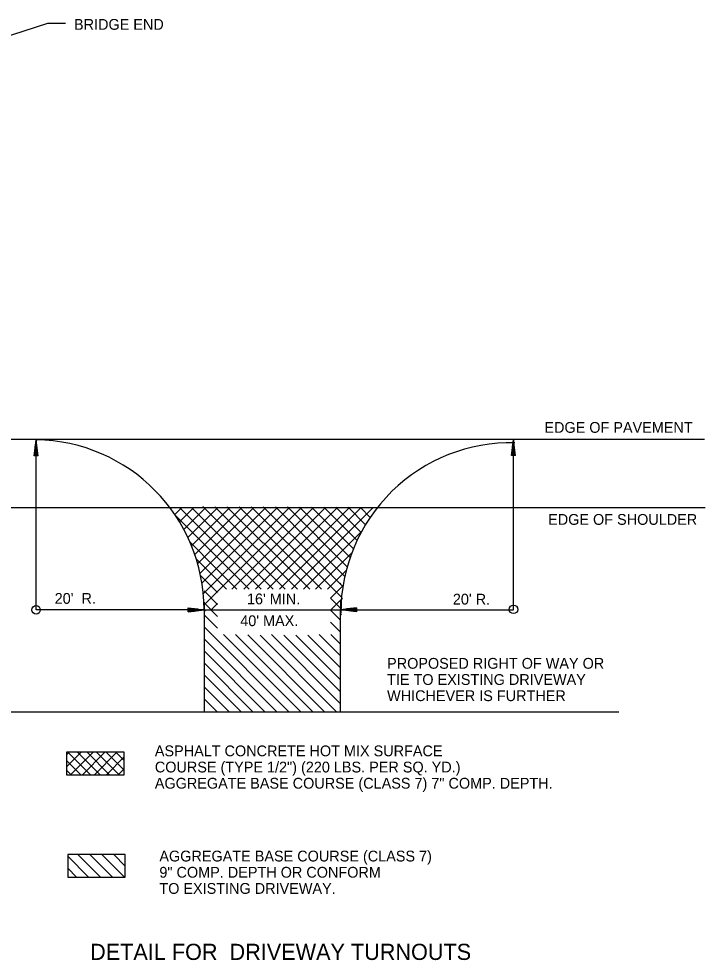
# Model space of a CAD drawing. Extents: x -2842 to 2681, y -2139 to 474.
# Drawn here: x -1653 to -1271, y -2139 to -1616 of the extents above; entities that cross this region are included whole.
import ezdxf

# ---------------------------------------------------------------- set-up
doc = ezdxf.new("R2010")
doc.units = 0
for name, color, linetype in [('B_County and Route', 7, 'Continuous'), ('B_Title Text', 7, 'Continuous'), ('R_Border', 7, 'Continuous'), ('R_Border Notes', 7, 'Continuous')]:
    doc.layers.add(name, color=color, linetype=linetype)

msp = doc.modelspace()

# ---------------------------------------------------------------- linework, layer by layer
at = {"layer": 'B_County and Route'}
for p, q in [((-1697.05, -1849.55), (-1271.3, -1849.55)), ((-1697.05, -1887.51), (-1270.98, -1887.51)), ((-1549.76, -1944.4), (-1549.76, -2001.23)), ((-1473.78, -2001.28), (-1473.78, -1944.17)), ((-1707.88, -2001.23), (-1318.99, -2001.23))]:
    msp.add_line(p, q, dxfattribs=at)
for points in [[(-1626.2, -2023.63), (-1626.2, -2036.17), (-1594.22, -2036.17), (-1594.22, -2023.63)], [(-1625.57, -2080.51), (-1625.57, -2093.05), (-1593.6, -2093.05), (-1593.6, -2080.51)]]:
    msp.add_lwpolyline(points, close=True, dxfattribs=at)
for centre, radius, start, end in [((-1644.4, -1944.55), 94.68, 0.0764, 89.2743), ((-1378.96, -1946.22), 94.72, 88.7538, 180)]:
    msp.add_arc(centre, radius, start, end, dxfattribs=at)
at = {"layer": 'B_Title Text'}
for p, q in [((-1516.65, -1907.12), (-1490.94, -1933)), ((-1503.31, -1907.18), (-1473.27, -1937.39)), ((-1554.04, -1916.3), (-1537.34, -1933)), ((-1543.32, -1921.14), (-1531.47, -1933)), ((-1484.84, -1919.09), (-1472.53, -1931.46)), ((-1551.64, -1925.36), (-1542.24, -1934.76)), ((-1549.76, -1933.91), (-1542.24, -1941.43)), ((-1549.76, -1940.24), (-1549.76, -1944.68)), ((-1549.76, -1940.58), (-1542.24, -1948.1)), ((-1479.42, -1937.9), (-1473.78, -1943.49)), ((-1473.78, -1938.93), (-1473.78, -1944.34)), ((-1549.76, -1947.25), (-1542.24, -1954.71)), ((-1479.42, -1944.57), (-1473.78, -1950.15)), ((-1479.42, -1951.24), (-1473.78, -1956.82)), ((-1549.76, -1953.92), (-1502.62, -2001.23)), ((-1549.76, -1960.59), (-1509.24, -2001.23)), ((-1538.88, -1958.13), (-1495.95, -2001.23)), ((-1532.21, -1958.13), (-1489.29, -2001.23)), ((-1525.42, -1958.36), (-1482.67, -2001.23)), ((-1518.53, -1958.59), (-1476, -2001.23)), ((-1512.31, -1958.13), (-1473.78, -1996.78)), ((-1505.36, -1958.48), (-1473.78, -1990.11)), ((-1498.69, -1958.48), (-1473.78, -1983.44)), ((-1492.02, -1958.53), (-1473.78, -1976.77)), ((-1485.75, -1958.13), (-1473.78, -1970.1)), ((-1479.14, -1958.13), (-1473.78, -1963.49)), ((-1549.76, -1967.2), (-1515.85, -2001.23)), ((-1549.76, -1973.87), (-1522.52, -2001.23)), ((-1549.76, -1980.54), (-1529.13, -2001.23)), ((-1549.76, -1987.2), (-1535.8, -2001.23)), ((-1549.76, -1993.87), (-1542.41, -2001.23))]:
    msp.add_line(p, q, dxfattribs=at)
for points in [[(-1566.01, -1891.44), (-1562.02, -1887.51)], [(-1563.44, -1887.51), (-1518.01, -1933)], [(-1563.39, -1895.49), (-1555.41, -1887.51)], [(-1560.99, -1899.77), (-1548.74, -1887.51)], [(-1558.71, -1904.16), (-1542.07, -1887.51)], [(-1556.77, -1887.51), (-1511.23, -1933)], [(-1556.72, -1908.77), (-1535.4, -1887.51)], [(-1554.89, -1913.62), (-1528.79, -1887.51)], [(-1553.3, -1918.63), (-1522.12, -1887.51)], [(-1551.99, -1923.99), (-1515.45, -1887.51)], [(-1550.9, -1929.58), (-1508.84, -1887.51)], [(-1550.5, -1887.06), (-1504.56, -1933)], [(-1550.16, -1935.45), (-1502.17, -1887.51)], [(-1543.78, -1887.11), (-1497.84, -1933)], [(-1541.04, -1933), (-1495.5, -1887.51)], [(-1537.05, -1887.11), (-1516.87, -1907.35)], [(-1534.37, -1933), (-1488.83, -1887.51)], [(-1530.27, -1887.17), (-1484.38, -1933)], [(-1527.7, -1933), (-1482.16, -1887.51)], [(-1523.54, -1887.17), (-1503.42, -1907.35)], [(-1521.09, -1933), (-1475.55, -1887.51)], [(-1516.82, -1887.17), (-1484.84, -1919.09)], [(-1514.42, -1933), (-1468.88, -1887.51)], [(-1510.09, -1887.23), (-1489.97, -1907.35)], [(-1507.75, -1933), (-1462.27, -1887.51)], [(-1503.36, -1887.23), (-1470.08, -1920.46)], [(-1501.08, -1933), (-1455.6, -1887.51)], [(-1496.58, -1887.28), (-1468.48, -1915.38)], [(-1489.91, -1887.28), (-1466.66, -1910.48)], [(-1483.19, -1887.28), (-1464.6, -1905.81)], [(-1476.4, -1887.28), (-1462.32, -1901.36)], [(-1469.62, -1887.34), (-1459.93, -1897.09)], [(-1462.78, -1887.51), (-1457.31, -1893.04)], [(-1565.49, -1892.24), (-1524.74, -1933)], [(-1494.47, -1933), (-1461.87, -1900.45)], [(-1557.51, -1906.89), (-1543.32, -1921.14)], [(-1489.97, -1907.35), (-1471.44, -1925.87)], [(-1487.8, -1933), (-1467.57, -1912.76)], [(-1481.13, -1933), (-1470.65, -1922.51)], [(-1549.76, -1928.1), (-1549.53, -1928.27)], [(-1479.42, -1937.9), (-1472.41, -1930.95)], [(-1474.29, -1929.63), (-1473.78, -1930.2)], [(-1549.76, -1941.66), (-1541.04, -1933)], [(-1549.76, -1934.76), (-1549.59, -1934.99)], [(-1474.29, -1936.47), (-1473.55, -1937.22)], [(-1549.76, -1941.49), (-1549.65, -1941.66)], [(-1545.77, -1944.4), (-1542.24, -1940.92)], [(-1479.25, -1944.4), (-1472.76, -1937.9)], [(-1549.65, -1944.74), (-1549.14, -1945.2)], [(-1474.29, -1943.2), (-1473.78, -1943.66)], [(-1474.01, -1946.56), (-1473.38, -1947.08)], [(-1626.2, -2025.05), (-1624.77, -2023.63)], [(-1626.2, -2031.66), (-1618.16, -2023.63)], [(-1625.52, -2023.63), (-1612.92, -2036.17)], [(-1624.03, -2036.17), (-1611.49, -2023.63)], [(-1620.16, -2023.63), (-1607.62, -2036.17)], [(-1617.42, -2036.17), (-1604.88, -2023.63)], [(-1614.86, -2023.63), (-1602.32, -2036.17)], [(-1610.75, -2036.17), (-1598.21, -2023.63)], [(-1609.5, -2023.63), (-1596.96, -2036.17)], [(-1604.2, -2023.63), (-1594.22, -2033.6)], [(-1598.9, -2023.63), (-1594.22, -2028.3)], [(-1626.2, -2028.24), (-1618.28, -2036.17)], [(-1604.08, -2036.17), (-1594.22, -2026.25)], [(-1626.2, -2033.54), (-1623.58, -2036.17)], [(-1597.47, -2036.17), (-1594.22, -2032.92)], [(-1625.57, -2081.48), (-1614, -2093.05)], [(-1619.93, -2080.51), (-1607.39, -2093.05)], [(-1613.26, -2080.51), (-1600.72, -2093.05)], [(-1606.59, -2080.51), (-1594.05, -2093.05)], [(-1599.98, -2080.51), (-1593.6, -2086.9)], [(-1625.57, -2088.15), (-1620.67, -2093.05)]]:
    msp.add_lwpolyline(points, dxfattribs=at)
at = {"layer": 'R_Border Notes'}
for p, q in [((-1644.33, -1858.72), (-1643.19, -1849.89)), ((-1643.41, -1858.72), (-1643.41, -1851.68)), ((-1643.19, -1944.4), (-1643.19, -1849.89)), ((-1643.19, -1849.89), (-1643.19, -1858.71)), ((-1642.04, -1858.71), (-1643.19, -1849.89)), ((-1642.96, -1858.71), (-1642.96, -1851.68)), ((-1378.76, -1858.6), (-1377.62, -1849.78)), ((-1377.84, -1858.6), (-1377.85, -1851.57)), ((-1377.62, -1944.4), (-1377.62, -1849.78)), ((-1377.62, -1849.78), (-1377.62, -1858.6)), ((-1376.47, -1858.6), (-1377.62, -1849.78)), ((-1377.39, -1858.6), (-1377.39, -1851.57)), ((-1644.1, -1858.72), (-1644.1, -1856.99)), ((-1643.87, -1858.72), (-1643.87, -1855.2)), ((-1643.64, -1858.72), (-1643.64, -1853.41)), ((-1642.73, -1858.72), (-1642.73, -1853.41)), ((-1642.49, -1858.71), (-1642.5, -1855.19)), ((-1642.26, -1858.72), (-1642.27, -1856.98)), ((-1378.54, -1858.6), (-1378.54, -1856.87)), ((-1378.31, -1858.6), (-1378.31, -1855.08)), ((-1378.08, -1858.61), (-1378.08, -1853.3)), ((-1377.16, -1858.6), (-1377.17, -1853.3)), ((-1376.93, -1858.6), (-1376.93, -1855.08)), ((-1376.7, -1858.6), (-1376.71, -1856.87)), ((-1642.04, -1858.71), (-1644.33, -1858.72)), ((-1376.47, -1858.6), (-1378.76, -1858.6)), ((-1549.76, -1944.4), (-1643.19, -1944.4)), ((-1558.59, -1943.26), (-1549.76, -1944.4)), ((-1558.58, -1945.55), (-1558.59, -1943.26)), ((-1558.59, -1943.48), (-1556.86, -1943.48)), ((-1558.59, -1943.71), (-1555.07, -1943.71)), ((-1558.59, -1943.94), (-1553.29, -1943.94)), ((-1558.59, -1944.18), (-1551.55, -1944.17)), ((-1549.76, -1944.4), (-1558.59, -1944.4)), ((-1558.59, -1944.86), (-1553.28, -1944.85)), ((-1558.59, -1945.32), (-1556.85, -1945.31)), ((-1558.58, -1945.55), (-1549.76, -1944.4)), ((-1558.58, -1944.63), (-1551.55, -1944.63)), ((-1558.58, -1945.09), (-1555.06, -1945.09)), ((-1549.76, -1944.4), (-1473.78, -1944.4)), ((-1464.96, -1943.25), (-1473.78, -1944.4)), ((-1473.78, -1944.4), (-1377.62, -1944.4)), ((-1473.78, -1944.4), (-1464.96, -1944.4)), ((-1464.96, -1945.54), (-1473.78, -1944.4)), ((-1464.96, -1944.17), (-1471.99, -1944.17)), ((-1464.96, -1944.62), (-1471.99, -1944.62)), ((-1464.96, -1943.94), (-1470.26, -1943.94)), ((-1464.95, -1944.85), (-1470.26, -1944.85)), ((-1464.96, -1943.71), (-1468.48, -1943.71)), ((-1464.95, -1945.08), (-1468.47, -1945.09)), ((-1464.96, -1943.48), (-1466.69, -1943.49)), ((-1464.95, -1945.31), (-1466.69, -1945.32)), ((-1464.96, -1943.25), (-1464.96, -1945.54))]:
    msp.add_line(p, q, dxfattribs=at)
msp.add_lwpolyline([(-1626.73, -1618.37), (-1636.79, -1618.37), (-1716.57, -1644.12)], dxfattribs=at)
for centre in [(-1643.21, -1944.43), (-1377.65, -1944.16)]:
    msp.add_circle(centre, 2.37, dxfattribs=at)

# ---------------------------------------------------------------- texts
at = {"layer": 'R_Border'}
for s, height, p in [('BRIDGE END', 6, (-1622.09, -1621.87)), ('EDGE OF PAVEMENT', 6, (-1360.41, -1846)), ('EDGE OF SHOULDER', 6, (-1358.33, -1897.16)), ("20'  R.", 6, (-1632.84, -1941.09)), ("16' MIN.", 6, (-1525.87, -1941.36)), ("20' R.", 6, (-1411.34, -1941.49)), ("40' MAX.", 6, (-1529.62, -1953.5)), ('PROPOSED RIGHT OF WAY OR', 6, (-1447.93, -1977.19)), ('TIE TO EXISTING DRIVEWAY', 6, (-1447.93, -1986.19)), ('WHICHEVER IS FURTHER', 6, (-1447.93, -1995.19)), ('ASPHALT CONCRETE HOT MIX SURFACE', 6, (-1577.13, -2025.86)), ('COURSE (TYPE 1/2") (220 LBS. PER SQ. YD.)', 6, (-1577.13, -2034.86)), ('AGGREGATE BASE COURSE (CLASS 7) 7" COMP. DEPTH.', 6, (-1577.13, -2043.86)), ('AGGREGATE BASE COURSE (CLASS 7)', 6, (-1574.6, -2084.37)), ('9" COMP. DEPTH OR CONFORM', 6, (-1574.6, -2093.37)), ('TO EXISTING DRIVEWAY.', 6, (-1574.6, -2102.37)), (' DETAIL FOR  DRIVEWAY TURNOUTS ', 9, (-1616.48, -2139.13))]:
    msp.add_text(s, height=height, dxfattribs=at).set_placement(p)

doc.saveas('drawing.dxf')
